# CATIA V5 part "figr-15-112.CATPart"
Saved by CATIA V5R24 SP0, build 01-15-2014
Part number: Part1
Bounding box of the stored display mesh (mm): x -55.37 to 68.649, y -21.457 to 35.984, z 0 to 57.441
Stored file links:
  D:\KAVITA\CATIA V5-6R2014 Project_ Kavita\CATIA V5-6R2014_partfiles\Partfiles\c15_catia_v5-6r2014_prt\figr-15-112.CATPart
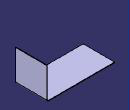
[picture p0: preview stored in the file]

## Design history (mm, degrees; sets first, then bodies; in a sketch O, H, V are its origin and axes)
SheetMetalParameters1: Thickness 1, BendRadius 2, KFactor 0.400515 {= log(min(100,max(20*SheetMetalParameters1.BendRadius,SheetMetalParameters1.Thickness)/SheetMetalParameters1.Thickness))/log(100)/2}, ReliefRadialLength 1, ReliefAxialLength 2, MinimumBendRadius 0
Body1 (main body)
  Sketch1 on xy-plane, origin (0, 0, 0), H (1, 0, 0), V (0, 1, 0)
    line L1 (-55.3695, 35.9836) -> (67.649, 35.9836)
    line L2 (67.649, 35.9836) -> (67.649, -21.4575)
    line L3 (67.649, -21.4575) -> (-55.3695, -21.4575)
    line L4 (-55.3695, -21.4575) -> (-55.3695, 35.9836)
    horizontal: L1 H, L3 H
    vertical: L2 V, L4 V
  Wall1: Thickness 1, Profile Sketch1
  d_NewWallOnEdge1: NewWallOnEdge_Edge edge [face of Wall1 | face of Wall1], NewWallOnEdge_Length 57.4411, NewWallOnEdge_HeightLimitOffset 0, NewWallOnEdge_WidthOffset1 0, NewWallOnEdge_WidthOffset2 0, NewWallOnEdge_Angle 90, NewWallOnEdge_BendRadiusValue 2 {= SheetMetalParameters1.BendRadius}, NewWallOnEdge_BendTable SheetMetalParameters1, KFacteur 0.400515 {= log(min(100,max(20*d_NewWallOnEdge1.Radius,SheetMetalParameters1.Thickness)/SheetMetalParameters1.Thickness))/log(100)/2}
